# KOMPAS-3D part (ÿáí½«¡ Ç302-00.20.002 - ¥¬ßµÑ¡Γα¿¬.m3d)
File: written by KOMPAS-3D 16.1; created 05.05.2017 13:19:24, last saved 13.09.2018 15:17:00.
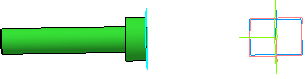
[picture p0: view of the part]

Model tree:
1. Эскиз:1
2. Операция выдавливания:1
     Расстояние 1 = 144.5
3. Эскиз:4
4. Операция выдавливания:3
     Расстояние 1 = 29
5. Смещенная плоскость:1
     Расстояние = 2.3
6. Эскиз:7
7. Вырезать элемент выдавливания:4
     Расстояние 1 = 1.4
8. Фаска:1
     Угол = 45; Длина 1 = 0.5; Длина 2 = 0.5
9. Массив по сетке:1  (with: Вырезать элемент выдавливания:4, Смещенная плоскость:1, Эскиз:7)  (2 pattern instances)
     Шаг 1 = 16.1; Угол раствора = 90; Номер 1 = 1
10. Эскиз:8
11. Операция вращения:1
     Угол 1 = 360
12. Фаска:2
     Угол = 45; Длина 1 = 1; Длина 2 = 1
13. Смещенная плоскость:3
     Расстояние = 20
14. Эскиз:10
15. Вырезать элемент выдавливания:6
     Расстояние 1 = 153.5
16. Эскиз:11
17. Вырезать элемент вращения:1  (labels: Сталь 40Х  ГОСТ 4543-71)
     Угол 1 = 360

Expressions: 25/2
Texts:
  Body Specification ( left align )
  Body Specificaton ( centered )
